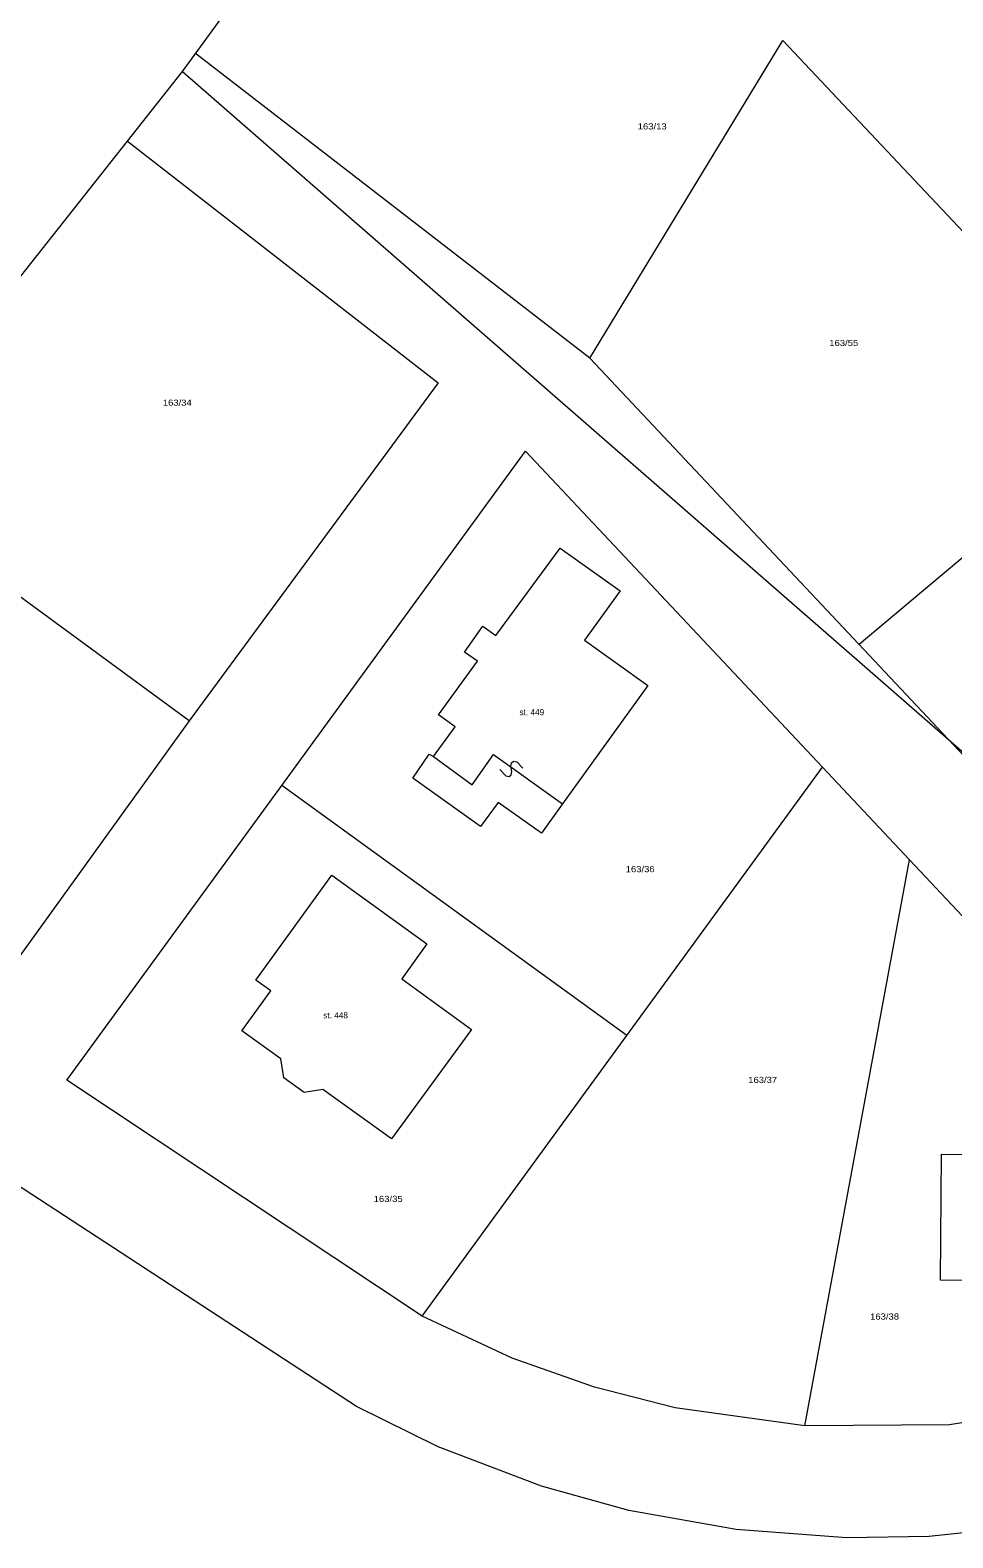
# Model space of a CAD drawing. Extents: x -694702 to -694000, y -1089746 to -1089192.
# Drawn here: x -694370.8 to -694295.8, y -1089656.2 to -1089533.7 of the extents above; entities that cross this region are included whole.
import ezdxf

# ---------------------------------------------------------------- set-up
doc = ezdxf.new("R2010")
doc.units = 0
doc.header["$LTSCALE"] = 0.2
doc.layers.add('50', color=7, linetype='Continuous', lineweight=13)
doc.layers.add('52', color=7, linetype='Continuous', lineweight=13)

msp = doc.modelspace()

# ---------------------------------------------------------------- linework, layer by layer
at = {"layer": '50'}
for p, q in [((-694358.38, -1089537.05), (-694334.75, -1089504.62)), ((-694325.28, -1089560.35), (-694309.59, -1089534.55)), ((-694309.59, -1089534.55), (-694261.1, -1089586)), ((-694325.28, -1089560.35), (-694357.33, -1089535.61)), ((-694362.87, -1089542.72), (-694358.38, -1089537.05)), ((-694358.38, -1089537.05), (-694296.16, -1089591.32)), ((-694296.16, -1089591.32), (-694325.28, -1089560.35)), ((-694281.04, -1089564.84), (-694303.39, -1089583.63)), ((-694357.85, -1089589.81), (-694384.62, -1089570.21)), ((-694357.85, -1089589.81), (-694375.13, -1089613.79)), ((-694296.16, -1089591.32), (-694278.77, -1089606.49)), ((-694280.61, -1089607.85), (-694296.16, -1089591.32)), ((-694337.99, -1089592.71), (-694334.85, -1089595.02)), ((-694334.85, -1089595.02), (-694333.11, -1089592.57)), ((-694333.11, -1089592.57), (-694327.51, -1089596.57)), ((-694322.27, -1089615.39), (-694306.37, -1089593.6)), ((-694306.37, -1089593.6), (-694299.3, -1089601.12)), ((-694322.27, -1089615.39), (-694350.33, -1089595.07)), ((-694307.8, -1089647.12), (-694299.3, -1089601.12)), ((-694338.91, -1089638.19), (-694322.27, -1089615.39))]:
    msp.add_line(p, q, dxfattribs=at)
for points in [[(-694412.22, -1089549.7), (-694384.62, -1089570.21), (-694362.87, -1089542.72), (-694337.6, -1089562.35), (-694357.85, -1089589.81)], [(-694350.33, -1089595.07), (-694330.52, -1089567.92), (-694306.37, -1089593.6)], [(-694176.61, -1089584.54), (-694202.56, -1089603.66), (-694228.51, -1089622.77), (-694251.47, -1089639.69), (-694259.12, -1089644.73), (-694263.81, -1089647.23), (-694269.12, -1089649.63), (-694276.14, -1089652.18), (-694282.15, -1089653.85), (-694288.71, -1089655.15), (-694297.74, -1089656.11), (-694304.42, -1089656.21), (-694313.38, -1089655.54), (-694322.1, -1089653.98), (-694329.22, -1089652.01), (-694337.6, -1089648.81), (-694344.26, -1089645.53), (-694373.32, -1089626.59), (-694380.67, -1089621.39)], [(-694338.91, -1089638.19), (-694367.8, -1089619.02), (-694350.33, -1089595.07)], [(-694299.3, -1089601.12), (-694264.93, -1089637.65), (-694273.26, -1089641.62), (-694283.94, -1089645.07), (-694296.06, -1089647.04), (-694307.8, -1089647.12)], [(-694307.8, -1089647.12), (-694318.35, -1089645.65), (-694324.91, -1089643.97), (-694331.6, -1089641.61), (-694338.91, -1089638.19)]]:
    msp.add_lwpolyline(points, dxfattribs=at)
for points in [[(-694334.42, -1089584.98), (-694335.48, -1089584.23), (-694333.99, -1089582.14), (-694332.91, -1089582.89), (-694327.69, -1089575.78), (-694322.82, -1089579.25), (-694325.71, -1089583.27), (-694320.56, -1089586.95), (-694327.51, -1089596.57), (-694329.2, -1089598.95), (-694332.74, -1089596.45), (-694334.16, -1089598.4), (-694339.68, -1089594.47), (-694338.34, -1089592.54), (-694337.99, -1089592.71), (-694336.24, -1089590.31), (-694337.59, -1089589.34)], [(-694352.42, -1089610.89), (-694346.24, -1089602.35), (-694338.52, -1089607.94), (-694340.56, -1089610.78), (-694334.91, -1089614.89), (-694341.4, -1089623.78), (-694346.98, -1089619.78), (-694348.5, -1089620.02), (-694350.16, -1089618.82), (-694350.41, -1089617.3), (-694353.58, -1089615), (-694351.21, -1089611.75)], [(-694296.71, -1089625.04), (-694283.49, -1089625.13), (-694283.56, -1089635.35), (-694296.78, -1089635.26)]]:
    msp.add_lwpolyline(points, close=True, dxfattribs=at)
at = {"layer": '52'}
msp.add_lwpolyline([(-694332.603, -1089593.77), (-694332.122, -1089594.279), (-694331.841, -1089594.334), (-694331.674, -1089594.221), (-694331.633, -1089593.94), (-694331.699, -1089593.498), (-694331.652, -1089593.224), (-694331.491, -1089593.103), (-694331.203, -1089593.151), (-694330.73, -1089593.667)], dxfattribs=at)

# ---------------------------------------------------------------- texts
at = {"layer": '52', "width": 1.15}
for s, p in [('163/13', (-694321.39, -1089541.77)), ('163/55', (-694305.82, -1089559.37)), ('163/34', (-694359.99, -1089564.22)), ('163/36', (-694322.37, -1089602.12)), ('163/37', (-694312.41, -1089619.25)), ('163/35', (-694342.85, -1089628.92)), ('163/38', (-694302.5, -1089638.48))]:
    msp.add_text(s, height=0.5, dxfattribs=at).set_placement(p)
at = {"layer": '52'}
for s, p in [('st. 449', (-694331, -1089589.37)), ('st. 448', (-694346.95, -1089614))]:
    msp.add_text(s, height=0.5, dxfattribs=at).set_placement(p)

doc.saveas('drawing.dxf')
